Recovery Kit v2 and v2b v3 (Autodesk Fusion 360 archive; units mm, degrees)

design "Recovery Kit v2 and v2b" references "6886K111_Flush-Mount 16 mm Panel-Mount Push-Button Switch", "1422N13_Panel-Mount Data Adapter", "6168T59_Push-In Signal Power Connectors(1)"
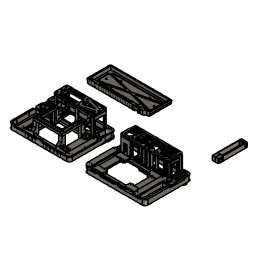
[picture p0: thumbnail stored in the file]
base_feature "Base Feature" bodies "doscher.com RK2B display bracket left", "doscher.com RK2B battery grid rear", "doscher.com RK2B battery grid long outer", "doscher.com RK2B battery grid center", "doscher.com RK2B battery grid short outer", "doscher.com RK2B battery grid front", "doscher.com RK2B battery pillar lower left", "doscher.com RK2B battery pillar lower right"
component_insert "Component Insert1"
component_insert "Component Insert2"
component_insert "Component Insert3"
component_insert "Component Insert4"
component_insert "Component Insert5"
component_insert "Component Insert6"
component_insert "Component Insert7"
component_insert "Component Insert8"
align "Align1"
align "Align2"
align "Align3"
align "Align4"
align "Align5"
move "Move1" TranslateX -110 TranslateY -180 TranslateZ 0
move "Move2" TranslateX 0 TranslateY -180 TranslateZ 0
move "Move3" TranslateX 0 TranslateY -180 TranslateZ 0
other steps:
step "Base Feature1"
step "Base Feature1"
step "Base Feature1"
step "Base Feature1"
step "Base Feature1"
step "Base Feature1" Linear Dimension-2 2.5 Linear Dimension-3 2.5 Diameter Dimension-2 6 Diameter Dimension-3 6 Linear Dimension-2 -7 Linear Dimension-3 7 Linear Dimension-4 7 Linear Dimension-5 7 Linear Dimension-6 7 Linear Dimension-7 7 Linear Dimension-8 7 Linear Dimension-9 80 Linear Dimension-10 80 Linear Dimension-11 80 Linear Dimension-12 80 Linear Dimension-13 80 Linear Dimension-14 80 Linear Dimension-15 3.5 Linear Dimension-16 -3.5 Linear Dimension-17 3.5 Linear Dimension-18 3.5 Linear Dimension-19 3.5 Linear Dimension-20 -3.5 Linear Dimension-21 3.5 Linear Dimension-22 -3.5 Linear Dimension-23 -3.5 Linear Dimension-24 3.5 Linear Dimension-25 -3.5 Linear Dimension-26 -3.5 Linear Dimension-27 3.5 Linear Dimension-28 -3.5 Linear Dimension-29 3.5 Linear Dimension-30 -3.5 Linear Dimension-2 -7 Linear Dimension-3 7 Linear Dimension-4 7 Linear Dimension-5 7 Linear Dimension-6 7 Linear Dimension-7 7 Linear Dimension-8 7 Distance 2 Linear Dimension-2 3.5 Linear Dimension-3 3.5 Diameter Dimension-2 3 Linear Dimension-4 3.5 Linear Dimension-5 3.5 Diameter Dimension-3 3 Linear Dimension-6 3.5 Linear Dimension-7 3.5 Diameter Dimension-4 3 Linear Dimension-8 3.5 Linear Dimension-9 3.5 Diameter Dimension-5 3 Linear Dimension-10 3.5 Linear Dimension-11 3.5 Diameter Dimension-6 3 Linear Dimension-12 3.5 Linear Dimension-13 3.5 Diameter Dimension-7 3 Distance 2 Distance 6 Linear Dimension-2 8.5 Distance 3 Distance 2 Distance 11 Linear Dimension-2 -8.951 Diameter Dimension-2 7 Diameter Dimension-2 2.8 Distance 2 Distance 2 Distance 5 mirrorStitchTolerance 0.1 mirrorStitchTolerance 0.1 mirrorStitchTolerance 0.1 Diameter Dimension-2 2.8 Diameter Dimension-2 2.8 Diameter Dimension-2 2.8 Linear Dimension-2 2 Diameter Dimension-2 1 Linear Dimension-3 20 Diameter Dimension-3 1 Linear Dimension-4 20 Diameter Dimension-4 1 Linear Dimension-2 59 Linear Dimension-3 49.5 Linear Dimension-4 59 Linear Dimension-6 3 Linear Dimension-6 3 Linear Dimension-7 9 Linear Dimension-8 55.5 Linear Dimension-9 3 Linear Dimension-10 55.5 Linear Dimension-2 3 Linear Dimension-3 3 Linear Dimension-4 3 Linear Dimension-5 3 Distance 2 Linear Dimension-2 5 Linear Dimension-3 10 Linear Dimension-4 5 Linear Dimension-5 10 Linear Dimension-6 10 Linear Dimension-7 10 Linear Dimension-8 10 Linear Dimension-9 10 Diameter Dimension-2 2.8 Diameter Dimension-3 2.8 Diameter Dimension-4 2.8 mirrorStitchTolerance 0.1 Linear Dimension-2 16 Linear Dimension-3 4 Linear Dimension-4 3 Linear Dimension-5 8 Linear Dimension-2 51.5 Linear Dimension-3 158 Linear Dimension-2 10 Linear Dimension-3 26 Distance 1 Distance 3 Linear Dimension-2 10 Linear Dimension-3 10 Linear Dimension-4 10 Linear Dimension-5 10 Linear Dimension-6 10 Linear Dimension-7 10 Linear Dimension-8 10 Linear Dimension-9 10 Linear Dimension-10 10 Linear Dimension-11 10 Linear Dimension-12 10 Linear Dimension-13 10 Linear Dimension-14 10 Linear Dimension-15 10 Linear Dimension-16 10 Linear Dimension-17 10 Linear Dimension-18 10 Linear Dimension-19 10 Linear Dimension-20 3 Distance 2 Distance 2 Distance 2 mirrorStitchTolerance 0.1 Distance 3 Diameter Dimension-2 6 Diameter Dimension-3 6 Linear Dimension-2 158.5 Linear Dimension-3 52 Distance 2 Distance 2 Distance 2 Distance 2 Linear Dimension-2 15 Linear Dimension-3 15 Diameter Dimension-2 3 Linear Dimension-4 42 Angular Dimension-2 0 Diameter Dimension-3 3 Linear Dimension-2 46 Linear Dimension-3 59 Distance 3 Angular Dimension-2 45 Angular Dimension-3 135 Angular Dimension-4 140 Distance 2.299 Distance 3 Distance 3 Linear Dimension-2 4 Linear Dimension-3 2 Distance 2 Distance 2 Distance 2 mirrorStitchTolerance 0.1 Linear Dimension-2 52 Diameter Dimension-2 2.8 Linear Dimension-2 10 Distance 3 Linear Dimension-2 8 Distance 3 Linear Dimension-2 1.5 Linear Dimension-3 1.5 Linear Dimension-2 13 Linear Dimension-3 1.5 Linear Dimension-4 1.5 Distance 2 Linear Dimension-2 1.5 Linear Dimension-3 13 Linear Dimension-4 1.5 Linear Dimension-5 13 Diameter Dimension-2 3 Diameter Dimension-3 3 Linear Dimension-2 7.39 Linear Dimension-3 7.39 Diameter Dimension-2 2.8 Diameter Dimension-3 2.8 Distance 2 Linear Dimension-2 7 Linear Dimension-3 5.7 Diameter Dimension-2 10.8 Distance 2 Distance 3 Diameter Dimension-2 3.5 Diameter Dimension-3 2.8 Diameter Dimension-4 3.5 Diameter Dimension-5 2.8 Distance 3 Diameter Dimension-2 18 Diameter Dimension-2 15 Linear Dimension-2 3 Distance 8 Distance 5 Distance 5 Linear Dimension-2 29 Linear Dimension-3 10 Distance 1 Linear Dimension-2 3 Linear Dimension-3 3 Distance 5 Distance 5 Distance 5 Distance 3 Distance 3 Distance 3 mirrorStitchTolerance 0.1 Distance 2 Distance 1 Distance 5 Distance 1 Distance 5 Distance 5 Linear Dimension-2 225 Linear Dimension-3 74 Linear Dimension-4 36.5 Linear Dimension-5 36.5 Linear Dimension-6 17.9 Linear Dimension-7 17.9 Linear Dimension-8 56 Linear Dimension-9 56 Linear Dimension-10 17.5 Linear Dimension-11 17.5 Linear Dimension-12 56 Linear Dimension-13 56 Linear Dimension-14 17.5 Linear Dimension-15 17.5 Diameter Dimension-2 1.8 Diameter Dimension-3 1.8 Diameter Dimension-4 1.8 Diameter Dimension-5 1.8 Diameter Dimension-6 1.8 Diameter Dimension-7 1.8 Linear Dimension-16 -5 Diameter Dimension-8 7 Diameter Dimension-9 7 Diameter Dimension-10 7 Diameter Dimension-11 7 Diameter Dimension-12 7 Diameter Dimension-13 7 Linear Dimension-2 -4 Distance 1 Distance 2 Linear Dimension-2 115 Linear Dimension-3 20 Linear Dimension-2 10 Diameter Dimension-2 15 Linear Dimension-2 -5 Linear Dimension-3 5 mirrorStitchTolerance 0.1 Linear Dimension-2 2 Distance 3 Distance 1 Linear Dimension-2 -3 mirrorStitchTolerance 0.1 Distance 3 Linear Dimension-2 33 Linear Dimension-3 10.5 Linear Dimension-4 7.8 Linear Dimension-2 3.4 Linear Dimension-2 23.5 Diameter Dimension-2 2 Linear Dimension-2 23.5 Diameter Dimension-2 2 Linear Dimension-2 23.5 Diameter Dimension-2 2 Linear Dimension-2 23.5 Diameter Dimension-2 2 Diameter Dimension-2 5 Diameter Dimension-3 5 Diameter Dimension-4 5 Diameter Dimension-5 5 Linear Dimension-2 7 Linear Dimension-3 7 Linear Dimension-4 7 Linear Dimension-5 7 Linear Dimension-2 7 Linear Dimension-3 7 Linear Dimension-4 4 Linear Dimension-2 7 Linear Dimension-3 7 Diameter Dimension-2 2.3 Linear Dimension-2 7 Linear Dimension-3 7 Diameter Dimension-2 2.3 Distance 7 Distance 1.5 Linear Dimension-2 2 Linear Dimension-3 2 Distance 1 TranslateX 0 TranslateY 600 TranslateZ 0 TranslateX 0 TranslateY 0 TranslateZ 50 TranslateX 0 TranslateY 0 TranslateZ 65 TranslateX -1.5 TranslateY 2 TranslateZ 0 TranslateX 1 TranslateY 0 TranslateZ 0 Diameter Dimension-2 5 Diameter Dimension-3 5 Diameter Dimension-4 5 Diameter Dimension-5 5 Diameter Dimension-6 5 Diameter Dimension-7 5 Distance 1.5 Linear Dimension-2 -2 Linear Dimension-2 17 Distance 8 Linear Dimension-2 8 Linear Dimension-3 8 Linear Dimension-4 8 Linear Dimension-5 8 Diameter Dimension-2 3.8 Diameter Dimension-3 3.8 Distance 2 Distance 2 Distance 2 Linear Dimension-2 15 Linear Dimension-3 4 Linear Dimension-4 15 Diameter Dimension-2 5 Linear Dimension-5 4 Linear Dimension-6 15 Linear Dimension-7 4 Linear Dimension-8 15 Linear Dimension-9 4 Diameter Dimension-3 5 Diameter Dimension-4 5 Linear Dimension-10 15 Linear Dimension-11 4 Diameter Dimension-5 5 Diameter Dimension-6 5 Linear Dimension-12 4 Diameter Dimension-7 5 Linear Dimension-13 4 Diameter Dimension-8 5 Linear Dimension-14 4 Diameter Dimension-9 5 Linear Dimension-15 4 Diameter Dimension-10 5 Distance 2 Distance 1 Distance 1 Linear Dimension-2 8 Linear Dimension-3 8 Linear Dimension-4 8 Linear Dimension-5 8 Diameter Dimension-2 3.8 Diameter Dimension-3 3.8 Linear Dimension-2 19 Linear Dimension-3 11.5 Diameter Dimension-2 3.8 Diameter Dimension-3 3.8 Distance 2 Linear Dimension-2 2 Linear Dimension-3 10 Linear Dimension-4 2 Linear Dimension-5 10 Distance 2 Distance 2 Distance 2 Linear Dimension-2 14 Linear Dimension-3 14 Linear Dimension-4 14 Linear Dimension-5 14 Linear Dimension-6 14 Linear Dimension-7 14 Linear Dimension-8 14 Linear Dimension-9 14 Linear Dimension-10 4 Linear Dimension-11 4 Linear Dimension-2 8 Linear Dimension-3 8 Linear Dimension-4 28.5 Linear Dimension-5 2 Linear Dimension-6 0.3 Linear Dimension-7 0.3 Linear Dimension-8 12 Linear Dimension-9 12 Distance 1 Distance 2 Distance 13 Distance 1 bodies "doscher.com RK2B display bracket left", "doscher.com RK2B battery grid rear", "doscher.com RK2B battery grid long outer", "doscher.com RK2B battery grid center", "doscher.com RK2B battery grid short outer", "doscher.com RK2B battery grid front", "doscher.com RK2B battery pillar lower left", "doscher.com RK2B battery pillar lower right"
component_insert "Extrude1" AlongDistance 75 TaperAngle 0
component_insert "Extrude2" AlongDistance 7 TaperAngle 0
step "MoveFace1"
step "MoveFace2"
step "Move1"
component_insert "Extrude3" AlongDistance -54 TaperAngle 0
component_insert "Extrude4" AlongDistance -2 TaperAngle 0
step "Base Feature2"
step "Move2"
step "OffsetFaces1" distance 25.5
component_insert "Extrude5" AlongDistance -0.1 TaperAngle 0
component_insert "Extrude6" AlongDistance -2 TaperAngle 0
component_insert "Extrude7" AlongDistance -4 TaperAngle 0
component_insert "Extrude8" AlongDistance -20 TaperAngle 0
step "Base Feature3" bodies "doscher.com RK2B cartridge cavity back"
step "Move3"
component_insert "Extrude9" AlongDistance -20 TaperAngle 0
step "Move4"
component_insert "Extrude10" AlongDistance -1 TaperAngle 0
component_insert "Extrude11" AlongDistance -2 TaperAngle 0
component_insert "Extrude12" AlongDistance 2 TaperAngle 0
component_insert "Extrude13" AlongDistance -6 TaperAngle 0
component_insert "Extrude14" AlongDistance -6 TaperAngle 0
component_insert "Extrude15" AlongDistance -6 TaperAngle 0
component_insert "Extrude16" AlongDistance 3 TaperAngle 0
component_insert "Extrude17" AlongDistance -35 TaperAngle 0
component_insert "Extrude18" AlongDistance -3 TaperAngle 0
step "MoveFace3"
step "Move5"
step "Move6"
step "CylinderPrimitive1" Height -35 Diameter 2.8
component_insert "Extrude19" AlongDistance -70 TaperAngle 0
component_insert "Extrude20" AlongDistance -10 TaperAngle 0
component_insert "Extrude21" AlongDistance -5 TaperAngle 0
component_insert "Extrude22" AlongDistance -10 TaperAngle 0
component_insert "Extrude23" AlongDistance -10 TaperAngle 0
component_insert "Extrude24" AlongDistance -2 TaperAngle 0
step "Move7"
step "Base Feature4" bodies "doscher.com RK2 display frame v5"
step "Move8"
step "Move9"
step "Move10"
step "Base Feature5"
step "Move11"
step "Move12"
step "MoveFace4"
component_insert "Extrude25" AlongDistance -4 TaperAngle 0
component_insert "Extrude26" AlongDistance 6 TaperAngle 0
component_insert "Extrude27" AlongDistance 6 TaperAngle 0
component_insert "Extrude28" AlongDistance -3 TaperAngle 0
step "MoveFace5"
component_insert "Extrude29" AlongDistance 2 TaperAngle 0
component_insert "Extrude30" AlongDistance 2 TaperAngle 0
component_insert "Extrude31" AlongDistance -4 TaperAngle 0
step "MoveFace6"
step "Move13"
step "MoveFace7"
component_insert "Extrude32" AlongDistance 2 TaperAngle 0
step "CylinderPrimitive2" Height -35 Diameter 3.8
step "CylinderPrimitive3" Height -35 Diameter 3.8
component_insert "Extrude33" AlongDistance -20 TaperAngle 0
component_insert "Extrude34" AlongDistance -15 TaperAngle 0
step "Move14"
step "CylinderPrimitive4" Height -54 Diameter 2.8
step "CylinderPrimitive5" Height 51 Diameter 2.8
step "CylinderPrimitive6" Height -54 Diameter 2.8
step "CylinderPrimitive7" Height 62 Diameter 2.8
step "CylinderPrimitive8" Height 90 Diameter 3.8
step "CylinderPrimitive9" Height 100 Diameter 3.8
component_insert "Extrude35" AlongDistance -57 TaperAngle 0
step "Move15"
component_insert "Extrude36" AlongDistance -19 TaperAngle 0
component_insert "Extrude37" AlongDistance 10 TaperAngle 0
component_insert "Extrude38" AlongDistance 3 TaperAngle 0
component_insert "Extrude39" AlongDistance -6 TaperAngle 0
component_insert "Extrude40" AlongDistance -3 TaperAngle 0
step "Fillet1" Radius 3
step "Fillet2" Radius 2
component_insert "Extrude41" AlongDistance -84 TaperAngle 0
component_insert "Extrude42" AlongDistance 1 TaperAngle 0
step "OffsetFaces2" distance 2
step "OffsetFaces3" distance 2
step "OffsetFaces4" distance 2
step "OffsetFaces5" distance 2
step "OffsetFaces6" distance -2
step "OffsetFaces7" distance -2
step "CylinderPrimitive10" Height -2 Diameter 2.8
step "CylinderPrimitive11" Height -2 Diameter 2.8
step "CylinderPrimitive12" Height -2 Diameter 2.8
step "Fillet3" Radius 7.5
step "Fillet4" Radius 7.5
step "Fillet5" Radius 3.25
step "CylinderPrimitive13" Height -1 Diameter 2.8
step "CylinderPrimitive14" Height -1 Diameter 2.8
step "Fillet6" Radius 8
step "Fillet7" Radius 8
step "CylinderPrimitive15" Height -1 Diameter 2.8
step "Base Feature6" bodies "doscher.com RK2 battery middle"
step "Move16"
component_insert "Extrude43" AlongDistance -15 TaperAngle 0
step "Move17"
component_insert "Extrude44" AlongDistance -5 TaperAngle 0
step "Fillet8" Radius 1
step "Fillet9" Radius 1
component_insert "Extrude45" AlongDistance 2 TaperAngle 0
step "Align1"
step "Move18"
step "Align2"
component_insert "Extrude46" AlongDistance -4 TaperAngle 0
step "Move19"
step "Move20"
step "Move21"
step "CylinderPrimitive16" Height 50 Diameter 2.8
step "CylinderPrimitive17" Height 24 Diameter 3
step "CylinderPrimitive18" Height 50 Diameter 3
step "CylinderPrimitive19" Height 50 Diameter 3
step "CylinderPrimitive20" Height 50 Diameter 3
step "CylinderPrimitive21" Height 26 Diameter 3
step "CylinderPrimitive22" Height 50 Diameter 3
step "CylinderPrimitive23" Height 50 Diameter 3
step "CylinderPrimitive24" Height 30 Diameter 3
step "CylinderPrimitive25" Height 50 Diameter 3
component_insert "Extrude47" AlongDistance -10 TaperAngle 0
component_insert "Extrude48" AlongDistance 1 TaperAngle 0
component_insert "Extrude49" AlongDistance 3 TaperAngle 0
step "CylinderPrimitive26" Height -3 Diameter 6
step "CylinderPrimitive27" Height -3 Diameter 6
step "CylinderPrimitive28" Height -3 Diameter 6
step "CylinderPrimitive29" Height -3 Diameter 6
step "CylinderPrimitive30" Height -3 Diameter 6
step "CylinderPrimitive31" Height -3 Diameter 6
step "CylinderPrimitive32" Height -3 Diameter 6
step "CylinderPrimitive33" Height -3 Diameter 6
step "CylinderPrimitive34" Height -3 Diameter 6
component_insert "Extrude50" AlongDistance -3 TaperAngle 0
component_insert "Extrude51" AlongDistance 2 TaperAngle 0
step "Move22"
component_insert "Extrude52" AlongDistance 1 TaperAngle 0
component_insert "Extrude53" AlongDistance 59 TaperAngle 0
component_insert "Extrude54" AlongDistance 9 TaperAngle 0
component_insert "Extrude55" AlongDistance 6 TaperAngle 0
component_insert "Extrude56" AlongDistance -13 TaperAngle 0
step "Fillet10" Radius 1
step "Fillet11" Radius 2
step "OffsetFaces8" distance 3
step "OffsetFaces9" distance 3
step "OffsetFaces10" distance 3
step "OffsetFaces11" distance 3
step "OffsetFaces12" distance 6
step "OffsetFaces13" distance 6
component_insert "Extrude57" AlongDistance -2 TaperAngle 0
component_insert "Extrude58" AlongDistance 1 TaperAngle 0
step "Base Feature7"
step "Move23"
component_insert "Extrude59" AlongDistance 0.6 TaperAngle 0
component_insert "Extrude60" AlongDistance -20 TaperAngle 0
component_insert "Extrude61" AlongDistance 0.6 TaperAngle 0
component_insert "Extrude62" AlongDistance 4 TaperAngle 0
component_insert "Extrude63" AlongDistance 4 TaperAngle 0
step "Base Feature8"
step "Move24"
step "Move25"
component_insert "Extrude64" AlongDistance -0.5 TaperAngle 0
component_insert "Extrude65" AlongDistance -0.5 TaperAngle 0
step "Move26"
step "OffsetFaces14" distance -0.5
step "OffsetFaces15" distance -0.5
step "OffsetFaces16" distance -0.5
component_insert "Extrude66" AlongDistance 2 TaperAngle 0
component_insert "Extrude67" AlongDistance 2 TaperAngle 0
component_insert "Extrude68" AlongDistance -20 TaperAngle 0
step "Move27"
component_insert "Extrude69" AlongDistance -2 TaperAngle 0
step "CylinderPrimitive35" Height -41 Diameter 27.5
step "CylinderPrimitive36" Height -29 Diameter 2.8
step "CylinderPrimitive37" Height -51 Diameter 2.8
step "CylinderPrimitive38" Height -43 Diameter 2.8
step "CylinderPrimitive39" Height -42 Diameter 2.8
step "CylinderPrimitive40" Height -59 Diameter 2.8
step "CylinderPrimitive41" Height -59 Diameter 2.8
step "CylinderPrimitive42" Height -37 Diameter 3
step "CylinderPrimitive43" Height -26 Diameter 3
step "CylinderPrimitive44" Height -25 Diameter 3
component_insert "Extrude70" AlongDistance -10 TaperAngle 0
component_insert "Extrude71" AlongDistance -1 TaperAngle 0
component_insert "Extrude72" AlongDistance -2 TaperAngle 0
component_insert "Extrude73" AlongDistance 1 TaperAngle 0
component_insert "Extrude74" AlongDistance 3 TaperAngle 0
component_insert "Extrude75" AlongDistance -15 TaperAngle 0
component_insert "Extrude76" AlongDistance 3 TaperAngle 0
step "Move28"
step "CylinderPrimitive45" Height 3 Diameter 5.5
step "CylinderPrimitive46" Height 2 Diameter 5.5
component_insert "Extrude77" AlongDistance -1 TaperAngle 0
step "CylinderPrimitive47" Height 2 Diameter 5.5
step "CylinderPrimitive48" Height -10 Diameter 3
step "CylinderPrimitive49" Height -10 Diameter 3
step "CylinderPrimitive50" Height -10 Diameter 3
component_insert "Extrude78" AlongDistance 35 TaperAngle 0
step "CylinderPrimitive51" Height 14 Diameter 23
step "CylinderPrimitive52" Height 43 Diameter 23
component_insert "Extrude79" AlongDistance -7 TaperAngle 0
step "OffsetFaces17" distance -15
component_insert "Extrude80" AlongDistance 15 TaperAngle 0
component_insert "Extrude81" AlongDistance -10 TaperAngle 0
component_insert "Extrude82" AlongDistance -2 TaperAngle 0
step "Move29"
step "OffsetFaces18" distance 15
step "MoveFace8"
component_insert "Extrude83" AlongDistance -2 TaperAngle 0
step "Align3"
step "Align4"
step "CylinderPrimitive53" Height 43 Diameter 3
step "CylinderPrimitive54" Height 30 Diameter 3
step "CylinderPrimitive55" Height 39 Diameter 3
step "OffsetFaces19" distance -22
step "CylinderPrimitive56" Height 36 Diameter 15.5
step "CylinderPrimitive57" Height 31 Diameter 15.5
step "CylinderPrimitive58" Height 41 Diameter 2.8
step "OffsetFaces20" distance 5
component_insert "Extrude84" AlongDistance -39 TaperAngle 0
component_insert "Extrude85" AlongDistance -3 TaperAngle 0
component_insert "Extrude86" AlongDistance -5 TaperAngle 0
component_insert "Extrude87" AlongDistance 3 TaperAngle 0
step "CylinderPrimitive59" Height -3 Diameter 5.5
step "CylinderPrimitive60" Height -3 Diameter 5.5
step "CylinderPrimitive61" Height -3 Diameter 5.5
component_insert "Extrude88" AlongDistance 3 TaperAngle 0
step "CylinderPrimitive62" Height -3 Diameter 5.5
step "CylinderPrimitive63" Height -3 Diameter 5.5
step "CylinderPrimitive64" Height -3 Diameter 5.5
step "CylinderPrimitive65" Height 3 Diameter 5.5
component_insert "Extrude89" AlongDistance 2 TaperAngle 0
step "OffsetFaces21" distance -2
component_insert "Extrude90" AlongDistance -15 TaperAngle 0
component_insert "Extrude91" AlongDistance -15 TaperAngle 0
step "Base Feature9" bodies "doscher.com RK2 PCB tray adapter"
step "Move30"
step "Align5"
step "Align6"
component_insert "Extrude92" AlongDistance 2 TaperAngle 0
component_insert "Extrude93" AlongDistance -18 TaperAngle 0
step "MoveFace9"
component_insert "Extrude94" AlongDistance -20 TaperAngle 0
step "CylinderPrimitive66" Height 50 Diameter 2.8
step "CylinderPrimitive67" Height 45 Diameter 2.8
component_insert "Extrude95" AlongDistance -63 TaperAngle 0
step "CylinderPrimitive68" Height 35 Diameter 5.5
step "OffsetFaces22" distance -1
step "OffsetFaces23" distance -1
step "OffsetFaces24" distance -1
step "OffsetFaces25" distance -3
step "Move31"
step "MoveFace10"
component_insert "Extrude96" AlongDistance 3 TaperAngle 0
step "OffsetFaces26" distance 2
step "MoveFace11"
component_insert "Extrude97" AlongDistance -57 TaperAngle 0
component_insert "Extrude98" AlongDistance 6 TaperAngle 0
step "CylinderPrimitive69" Height 50 Diameter 2.8
step "CylinderPrimitive70" Height 49 Diameter 2.8
component_insert "Extrude99" AlongDistance -44 TaperAngle 0
component_insert "Extrude100" AlongDistance 1.5 TaperAngle 0
component_insert "Extrude101" AlongDistance 1 TaperAngle 0
component_insert "Extrude102" AlongDistance -58 TaperAngle 0
step "MoveFace12"
step "CylinderPrimitive71" Height 35 Diameter 27.5
step "MoveFace13"
step "MoveFace14"
step "CylinderPrimitive72" Height 42 Diameter 2.8
step "CylinderPrimitive73" Height 42 Diameter 2.8
step "CylinderPrimitive74" Height 37 Diameter 2.8
step "CylinderPrimitive75" Height 42 Diameter 2.8
component_insert "Extrude103" AlongDistance -4 TaperAngle 0
component_insert "Extrude104" AlongDistance -6 TaperAngle 0
step "CylinderPrimitive76" Height 40 Diameter 27.5
component_insert "Extrude105" AlongDistance -7 TaperAngle 0
step "OffsetFaces27" distance 3
step "CylinderPrimitive77" Height -60 Diameter 2.8
step "CylinderPrimitive78" Height -3 Diameter 5.5
step "CylinderPrimitive79" Height -3 Diameter 5.5
component_insert "Extrude106" AlongDistance 12 TaperAngle 0
step "CylinderPrimitive80" Height -26 Diameter 2.8
component_insert "Extrude107" AlongDistance 5 TaperAngle 0
step "CylinderPrimitive81" Height -50 Diameter 11.1
step "OffsetFaces28" distance -2
component_insert "Extrude108" AlongDistance 10 TaperAngle 0
component_insert "Extrude109" AlongDistance -1.5 TaperAngle 0
step "OffsetFaces29" distance 3
step "CylinderPrimitive82" Height -20 Diameter 5
step "CylinderPrimitive83" Height -10 Diameter 5
component_insert "Extrude110" AlongDistance -5 TaperAngle 0
step "MoveFace15"
step "OffsetFaces30" distance 2
step "Move32"
step "Move33"
step "Move34"
component_insert "Extrude111" AlongDistance 5 TaperAngle 0
component_insert "Extrude112" AlongDistance 5 TaperAngle 0
component_insert "Extrude113" AlongDistance 5 TaperAngle 0
component_insert "Extrude114" AlongDistance 5 TaperAngle 0
step "MoveFace16"
step "Move35"
step "Move36"
step "Move37"
step "Align7"
step "Align8"
component_insert "Extrude115" AlongDistance -60 TaperAngle 0
component_insert "Extrude116" AlongDistance 5 TaperAngle 0
step "CylinderPrimitive84" Height -4 Diameter 2.8
step "CylinderPrimitive85" Height -4 Diameter 2.8
step "CylinderPrimitive86" Height -4 Diameter 2.8
step "CylinderPrimitive87" Height -4 Diameter 2.8
component_insert "Extrude117" AlongDistance 5 TaperAngle 0
component_insert "Extrude118" AlongDistance 5 TaperAngle 0
step "CylinderPrimitive88" Height -3 Diameter 2.8
step "CylinderPrimitive89" Height -3 Diameter 2.8
step "CylinderPrimitive90" Height -3 Diameter 2.8
step "CylinderPrimitive91" Height -3 Diameter 2.8
component_insert "Extrude119" AlongDistance -2 TaperAngle 0
component_insert "Extrude120" AlongDistance -2 TaperAngle 0
component_insert "Extrude121" AlongDistance -2 TaperAngle 0
component_insert "Extrude122" AlongDistance -2 TaperAngle 0
step "Base Feature10"
component_insert "Extrude123" AlongDistance 5 TaperAngle 0
component_insert "Extrude124" AlongDistance 3 TaperAngle 0
step "CylinderPrimitive92" Height 2 Diameter 7
step "CylinderPrimitive93" Height 2 Diameter 7
step "CylinderPrimitive94" Height 2 Diameter 7
step "CylinderPrimitive95" Height 2 Diameter 7
step "CylinderPrimitive96" Height 2 Diameter 7
step "CylinderPrimitive97" Height 2 Diameter 7
step "CylinderPrimitive98" Height -50 Diameter 1.8
step "CylinderPrimitive99" Height -50 Diameter 1.8
step "CylinderPrimitive100" Height -50 Diameter 1.8
step "CylinderPrimitive101" Height -80 Diameter 1.8
step "CylinderPrimitive102" Height -50 Diameter 1.8
step "CylinderPrimitive103" Height -50 Diameter 1.8
component_insert "Extrude125" AlongDistance -3 TaperAngle 0
component_insert "Extrude126" AlongDistance 5 TaperAngle 0
component_insert "Extrude127" AlongDistance 2 TaperAngle 0
component_insert "Extrude128" AlongDistance 20 TaperAngle 0
component_insert "Extrude129" AlongDistance 10 TaperAngle 0
component_insert "Extrude130" AlongDistance -10 TaperAngle 0
component_insert "Extrude131" AlongDistance -12 TaperAngle 0
step "Fillet12" Radius 2
step "Fillet13" Radius 5
component_insert "Extrude132" AlongDistance -27 TaperAngle 0
step "Move38" TranslateX 110 TranslateY 0 TranslateZ 0
step "OffsetFaces31" distance -1
component_insert "Extrude133" AlongDistance 5 TaperAngle 0
component_insert "Extrude134" AlongDistance -15 TaperAngle 0
component_insert "Extrude135" AlongDistance -3 TaperAngle 0
component_insert "Extrude136" AlongDistance -50 TaperAngle 0
step "OffsetFaces32" distance -0.1
step "OffsetFaces33" distance -0.1
component_insert "Extrude137" AlongDistance -0.5 TaperAngle 0
component_insert "Extrude138" AlongDistance -0.5 TaperAngle 0
component_insert "Extrude139" AlongDistance -7 TaperAngle 0
component_insert "Extrude140" AlongDistance -9 TaperAngle 0
component_insert "Extrude141" AlongDistance 0.5 TaperAngle 0
component_insert "Extrude142" AlongDistance 0.5 TaperAngle 0
component_insert "Extrude143" AlongDistance -2 TaperAngle 0
component_insert "Extrude144" AlongDistance -7.5 TaperAngle 0
component_insert "Extrude145" AlongDistance -2 TaperAngle 0
component_insert "Extrude146" AlongDistance -2 TaperAngle 0
component_insert "Extrude147" AlongDistance -5 TaperAngle 0
component_insert "Extrude148" AlongDistance 1.9 TaperAngle 0
component_insert "Extrude149" AlongDistance 1.9 TaperAngle 0
component_insert "Extrude150" AlongDistance -20 TaperAngle 0
component_insert "Extrude151" AlongDistance -2 TaperAngle 0
component_insert "Extrude152" AlongDistance -10 TaperAngle 0
component_insert "Extrude153" AlongDistance -2 TaperAngle 0
component_insert "Extrude154" AlongDistance 2 TaperAngle 0
component_insert "Extrude155" AlongDistance 7 TaperAngle 0
component_insert "Extrude156" AlongDistance -7 TaperAngle 0
component_insert "Extrude157" AlongDistance -15 TaperAngle 0
component_insert "Extrude158" AlongDistance -10 TaperAngle 0
component_insert "Extrude159" AlongDistance -5 TaperAngle 0
component_insert "Extrude160" AlongDistance -5 TaperAngle 0
step "OffsetFaces34" distance -2
step "MoveFace17" TranslateX 2 TranslateY 0 TranslateZ 0
step "OffsetFaces35" distance -2
component_insert "Extrude161" AlongDistance -7 TaperAngle 0
component_insert "Extrude162" AlongDistance -2 TaperAngle 0
component_insert "Extrude163" AlongDistance -2 TaperAngle 0
component_insert "Extrude164" AlongDistance 1.25 TaperAngle 0
component_insert "Extrude165" AlongDistance 1.25 TaperAngle 0
step "MoveFace18" TranslateX -1 TranslateY -1 TranslateZ 0
step "MoveFace19" TranslateX 0 TranslateY -1 TranslateZ 0
step "MoveFace20" TranslateX 1 TranslateY 0 TranslateZ 0
component_insert "Extrude166" AlongDistance -10 TaperAngle 0
step "CylinderPrimitive104" Height -50 Diameter 2.1
step "CylinderPrimitive105" Height -50 Diameter 2.1
step "CylinderPrimitive106" Height -50 Diameter 2.1
step "CylinderPrimitive107" Height -50 Diameter 2.1
step "CylinderPrimitive108" Height -50 Diameter 2.1
step "CylinderPrimitive109" Height -50 Diameter 2.1
step "CylinderPrimitive110" Height -145 Diameter 1
step "MoveFace21"
step "MoveFace22" TranslateX 0.1 TranslateY -1.5 TranslateZ 0
step "CylinderPrimitive111" Height -96 Diameter 1
component_insert "Extrude167" AlongDistance 40 TaperAngle 0
step "Move39" TranslateX 0.1 TranslateY -1.5 TranslateZ 0
step "CylinderPrimitive112" Height -200 Diameter 1
step "MoveFace23" TranslateX -0.3 TranslateY -1 TranslateZ 0
step "CylinderPrimitive113" Height -100 Diameter 1
step "CylinderPrimitive114" Height -500 Diameter 1
step "CylinderPrimitive115" Height -500 Diameter 1
step "Move40" TranslateX -0.1 TranslateY -1.5 TranslateZ 0
step "Move41" TranslateX -0.1 TranslateY -1.5 TranslateZ 0
step "Move42" TranslateX 1.2 TranslateY 0 TranslateZ 0
step "Move43" TranslateX 0.1 TranslateY -1 TranslateZ 0
step "Move44" TranslateX -1.5 TranslateY 2 TranslateZ 0
step "Move45" TranslateX 1 TranslateY 0 TranslateZ 0
step "CylinderPrimitive116" Height -10 Diameter 2.2
step "CylinderPrimitive117" Height -10 Diameter 2.2
step "CylinderPrimitive118" Height -10 Diameter 2.2
step "CylinderPrimitive119" Height -10 Diameter 2.2
step "CylinderPrimitive120" Height -10 Diameter 2.2
step "CylinderPrimitive121" Height -10 Diameter 2.2
component_insert "Extrude168" AlongDistance 2 TaperAngle 0
step "Base Feature11"
step "Move46" TranslateX 0 TranslateY -9 TranslateZ 0
step "CylinderPrimitive122" Height 11 Diameter 2
component_insert "Extrude169" AlongDistance 8 TaperAngle 0
component_insert "Extrude170" AlongDistance 2 TaperAngle 0
component_insert "Extrude171" AlongDistance 1 TaperAngle 0
component_insert "Extrude172" AlongDistance 8 TaperAngle 0
component_insert "Extrude173" AlongDistance 8 TaperAngle 0
component_insert "Extrude174" AlongDistance -5 TaperAngle 0
component_insert "Extrude175" AlongDistance 2 TaperAngle 0
component_insert "Extrude176" AlongDistance -30 TaperAngle 0
component_insert "Extrude177" AlongDistance -5 TaperAngle 0
component_insert "Extrude178" AlongDistance 5 TaperAngle 0
component_insert "Extrude179" AlongDistance -5 TaperAngle 0
step "CylinderPrimitive123" Height -50 Diameter 2.5
step "CylinderPrimitive124" Height -50 Diameter 2.5
step "Base Feature12" bodies "doscher.com RK2 and RK2B keyboard enclosure"
step "Move47"
component_insert "Extrude180" AlongDistance -110 TaperAngle 0
component_insert "Extrude181" AlongDistance -1 TaperAngle 0
component_insert "Extrude182" AlongDistance 106 TaperAngle 0
component_insert "Extrude183" AlongDistance 2 TaperAngle 0
step "Fillet14" Radius 3
step "Fillet15" Radius 3
component_insert "Extrude184" AlongDistance 5 TaperAngle 0
step "Move48" TranslateX 0 TranslateY 0 TranslateZ 13
component_insert "Extrude185" AlongDistance 3 TaperAngle 0
component_insert "Extrude186" AlongDistance 6.5 TaperAngle 0
component_insert "Extrude187" AlongDistance -0.336 TaperAngle 0
component_insert "Extrude188" AlongDistance -0.305 TaperAngle 0
component_insert "Extrude189" AlongDistance -6 TaperAngle 0
step "Move49" TranslateX 0 TranslateY -16 TranslateZ 0
component_insert "Extrude190" AlongDistance 2 TaperAngle 0
component_insert "Extrude191" AlongDistance 3 TaperAngle 0
step "CylinderPrimitive125" Height 23 Diameter 4
step "CylinderPrimitive126" Height 24 Diameter 4
step "CylinderPrimitive127" Height 22 Diameter 4
step "CylinderPrimitive128" Height 25 Diameter 4
step "Move50" TranslateX 0 TranslateY 16 TranslateZ 0
component_insert "Extrude192" AlongDistance -1 TaperAngle 0
component_insert "Extrude193" AlongDistance -2 TaperAngle 0
step "Base Feature13" bodies "doscher.com RK2B battery retainer loop"
step "Move51"
component_insert "Extrude194" AlongDistance -3 TaperAngle 0
component_insert "Extrude195" AlongDistance 24 TaperAngle 0
step "MoveFace24"
component_insert "Extrude196" AlongDistance 2 TaperAngle 0
step "CylinderPrimitive129" Height 2 Diameter 7.8
step "CylinderPrimitive130" Height -6 Diameter 3.1
step "Base Feature14" bodies "doscher.com RK2B flat display frame"
step "Move52"
component_insert "Extrude197" AlongDistance -34 TaperAngle 0
component_insert "Extrude198" AlongDistance -25 TaperAngle 0
component_insert "Extrude199" AlongDistance -20 TaperAngle 0
component_insert "Extrude200" AlongDistance -14 TaperAngle 0
component_insert "Extrude201" AlongDistance -16 TaperAngle 0
component_insert "Extrude202" AlongDistance -1 TaperAngle 0
component_insert "Extrude203" AlongDistance -1 TaperAngle 0
component_insert "Extrude204" AlongDistance -1 TaperAngle 0
step "OffsetFaces36" distance -3
component_insert "Extrude205" AlongDistance -1 TaperAngle 0
step "CreateComponent1"
step "CreateComponent2"
step "CreateComponent6"
step "CreateComponent1"
step "CreateComponent2"
step "CreateComponent3"
step "CopyPasteBodies1"
step "CopyPasteBodies2"
step "CopyPasteBodies3"
step "CopyPasteBodies4"
step "CopyPasteBodies5"
step "CopyPasteBodies6"
step "CopyPasteBodies7"
step "CopyPasteBodies8"
step "CopyPasteBodies9"
step "CopyPasteBodies10"
step "CopyPasteBodies11"
step "CopyPasteBodies12"
step "CopyPasteBodies13"
named bodies: "doscher.com RK2B display bracket left", "doscher.com RK2B battery grid rear", "doscher.com RK2B battery grid long outer", "doscher.com RK2B battery grid center", "doscher.com RK2B battery grid short outer", "doscher.com RK2B battery grid front", "doscher.com RK2B battery pillar lower left", "doscher.com RK2B battery pillar lower right", "doscher.com RK2B battery pillar top left", "doscher.com RK2B battery pillar top center", "doscher.com RK2B battery pillar top right", "doscher.com RK2B display bracket right", "doscher.com RK2B primary frame", "doscher.com RK2B cartridge cavity back", "doscher.com RK2 primary frame", "doscher.com RK2 display frame v5", "doscher.com RK2 display bracket right", "doscher.com RK2 display bracket left", "doscher.com RK2 battery short end", "doscher.com RK2 battery middle", "doscher.com RK2 battery long end", "doscher.com RK2 battery rear", "doscher.com RK2 battery front", "doscher.com RK2 battery clip left", "doscher.com RK2 battery clip right", "doscher.com RK2 PCB tray adapter", "doscher.com RK2 and RK2B keyboard shim A", "doscher.com RK2 and RK2B keyboard shim B", "doscher.com RK2 and RK2B keyboard enclosure", "doscher.com RK2 and RK2B keyboard enclosure bracket", "doscher.com RK2B battery retainer loop", "doscher.com RK2B flat display frame"

design "6168T59_Push-In Signal Power Connectors(1)"
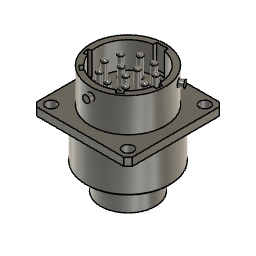
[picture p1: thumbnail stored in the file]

design "1422N13_Panel-Mount Data Adapter"
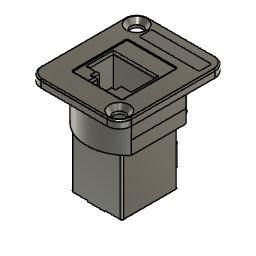
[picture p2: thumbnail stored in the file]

design "6886K111_Flush-Mount 16 mm Panel-Mount Push-Button Switch"
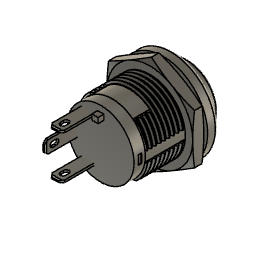
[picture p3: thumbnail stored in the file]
